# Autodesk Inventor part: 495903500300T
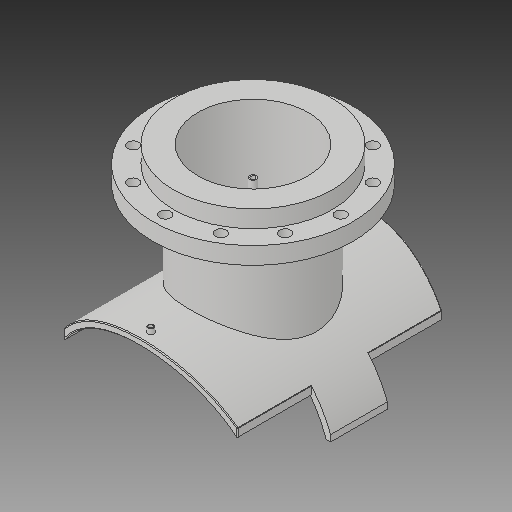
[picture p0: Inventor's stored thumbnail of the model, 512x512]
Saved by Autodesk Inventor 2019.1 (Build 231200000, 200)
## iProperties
Created: 2017-10
Part Number: 495903500300T
Material: Generic
Description: PLASSON FLANGED BRANCH SADDLE 500X300
Document SubType Name: Modeling
Designer: KIM
Mass: 2339.99 g
Surface Area: 3251.55 cm^2
Volume: 2339.99 cm^3
Density: 1 g/cm^3
Appearance: Default
Author: KIM
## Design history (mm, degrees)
derived "495904_495903.ipt"
feature "Solid1::495904_495903.ipt"
feature "Solid2::495904_495903.ipt"
tag "TaggingFeature1"
body "Solid1"
other parameters: "d1" = 15, "d2" = 405, "d4" = 0, "d6" = 132.5, "d7" = 0, "d12" = 275.6, "d13" = 14, "d14" = 238.5, "d16" = 5 deg, "d18" = 4, "d19" = 14, "d20" = 0, "d21" = 3, "d22" = 0, "d36" = 238.5, "d38" = 0, "d39" = 2, "d41" = 257, "d43" = 467, "d46" = 296, "d47" = 16, "d48" = 10.4, "d49" = 192.5, "d53" = 0, "d54" = 26, "d55" = 205, "d57" = 0, "d59" = 360 deg, "d63" = 0, "d66" = 275, "d67" = 15, "d68" = 137.5, "d70" = 0, "d71" = 2, "H_" = 275, "x_" = 15, "D_" = 16, "DN_" = 257, "D_1" = 467, "s_" = 26
